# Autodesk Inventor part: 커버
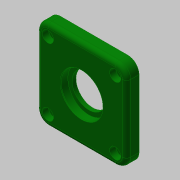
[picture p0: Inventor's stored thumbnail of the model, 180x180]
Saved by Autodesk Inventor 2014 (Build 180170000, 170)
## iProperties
Created: 2019-09
Part Number: 커버
Material: 알루미늄 6061
Document SubType Name: Modeling
Designer: mduedu
Density: 1 g/cm^3
Appearance: 진녹색
Author: mduedu
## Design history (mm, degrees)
sketch "스케치1"
  geometry: L1 (-32, -32)-(32, -32); L2 (32, -32)-(32, 32); L3 (32, 32)-(-32, 32); L4 (-32, 32)-(-32, -32); L5 (-32, -32)-(32, 32); L6 (32, -32)-(-32, 32); 1 further point
  constraints: 12 end point, 2 midpoint, 2 parallel, 1 horizontal, 1 perpendicular
  dimensions: "d44" = 64 distance of L3.end L2.end; "d45" = 64 distance of L2.end L1.end
extrude "돌출1" new body sketch "스케치1" distance "d1" = 9; taper "d2" = 0 deg
sketch "스케치2"
  geometry: C1 r 21 at (0, 0); 1 further point
  constraints: 1 centre point, 1 coincident
  dimensions: "d3" = 42 diameter of C1
extrude "돌출2" join sketch "스케치2" distance "d4" = 3; taper "d5" = 0 deg
hole "구멍1" diameter "d8" = 24; stored, may be unused: countersink angle "d12" = 90 deg, drill point angle "d14" = 118 deg; dims "d9" = 6, "d10" = 30, "d11" = 5.2, "d13" = 8, "d46" = 10, "d47" = 10
hole "구멍2" diameter "d17" = 37; stored, may be unused: countersink angle "d21" = 90 deg, drill point angle "d23" = 0 deg; dims "d15" = 10, "d16" = 10, "d18" = 6, "d19" = 30, "d20" = 5.2, "d22" = 4
fillet "모깎기1" dims "d24" = 3
fillet "모깎기4" dims "d48" = 8
fillet "모깎기2" dims "d25" = 3
chamfer "모따기1" distance "d27" = 0.5; stored, may be unused: second distance "d28" = 2, angle "d29" = 30 deg
chamfer "모따기2" distance "d30" = 1; stored, may be unused: second distance "d31" = 2, angle "d32" = 30 deg
sketch "스케치4"
  geometry: A1 r 8 centre (-24, 24) between (-24, 32) and (-32, 24) reference; A2 r 8 centre (24, 24) between (32, 24) and (24, 32) reference; A3 r 8 centre (24, -24) between (24, -32) and (32, -24) reference; A4 r 8 centre (-24, -24) between (-32, -24) and (-24, -32) reference; 5 further points
  constraints: 4 coincident
hole "구멍4" sketch "스케치4" at (-24, 24), (24, 24), (24, -24), (-24, -24) diameter "d49" = 4.5; stored, may be unused: countersink angle "d53" = 90 deg, drill point angle "d55" = 118 deg; dims "d50" = 6, "d51" = 8, "d52" = 4.4, "d54" = 8
node "솔리드1"
